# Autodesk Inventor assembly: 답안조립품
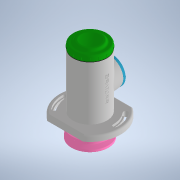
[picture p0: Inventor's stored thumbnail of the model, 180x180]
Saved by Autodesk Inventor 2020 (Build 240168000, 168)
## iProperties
Created: 2022-05
Part Number: 답안조립품
Document SubType Name: Assembly
Designer: Student
Author: Student
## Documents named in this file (22)
- C:\Users\Student\Desktop\720506V1028\답안조립품.iam
- C:\Users\Student\Desktop\720506V1028\본체.ipt
- C:\Users\Student\Desktop\720506V1028\개스킷.ipt
- C:\Users\Student\Desktop\720506V1028\사이드 커버.ipt
- 사이드 커버.ipt
- C:\Users\Student\Desktop\720506V1028\축.ipt
- C:\Users\Student\Desktop\720506V1028\멈춤링 15 x 1.ipt
- C:\Users\Student\Desktop\720506V1028\멈춤링 35 x 1.6.ipt
- C:\Users\Student\Desktop\720506V1028\베어링 6202.ipt
- C:\Users\Student\Desktop\720506V1028\부시1.ipt
- C:\Users\Student\Desktop\720506V1028\부시2.ipt
- C:\Users\Student\Desktop\720506V1028\와셔 10 x 21.ipt
- C:\Users\Student\Desktop\720506V1028\너트 M10.ipt
- C:\Users\Student\Desktop\720506V1028\오일 실 15 x 30 x 7.ipt
- C:\Users\Student\Desktop\720506V1028\키 4 x 4.ipt
- C:\Users\Student\Desktop\720506V1028\V-벨트풀리.ipt
- C:\Users\Student\Desktop\720506V1028\멈춤나사 M3.ipt
- C:\Users\Student\Desktop\720506V1028\와셔 4 x 16.ipt
- C:\Users\Student\Desktop\720506V1028\볼트 M4 x 10.ipt
- C:\Users\Student\Desktop\720506V1028\탑 커버.ipt
- C:\Users\Student\Desktop\720506V1028\와셔 3 x 6.ipt
- C:\Users\Student\Desktop\720506V1028\십자볼트 M3 x 10.ipt
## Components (3 placed, 3 different names)
1. 개스킷:1
2. V-벨트풀리:1
3. ISO 4017 M4 x 10:1
